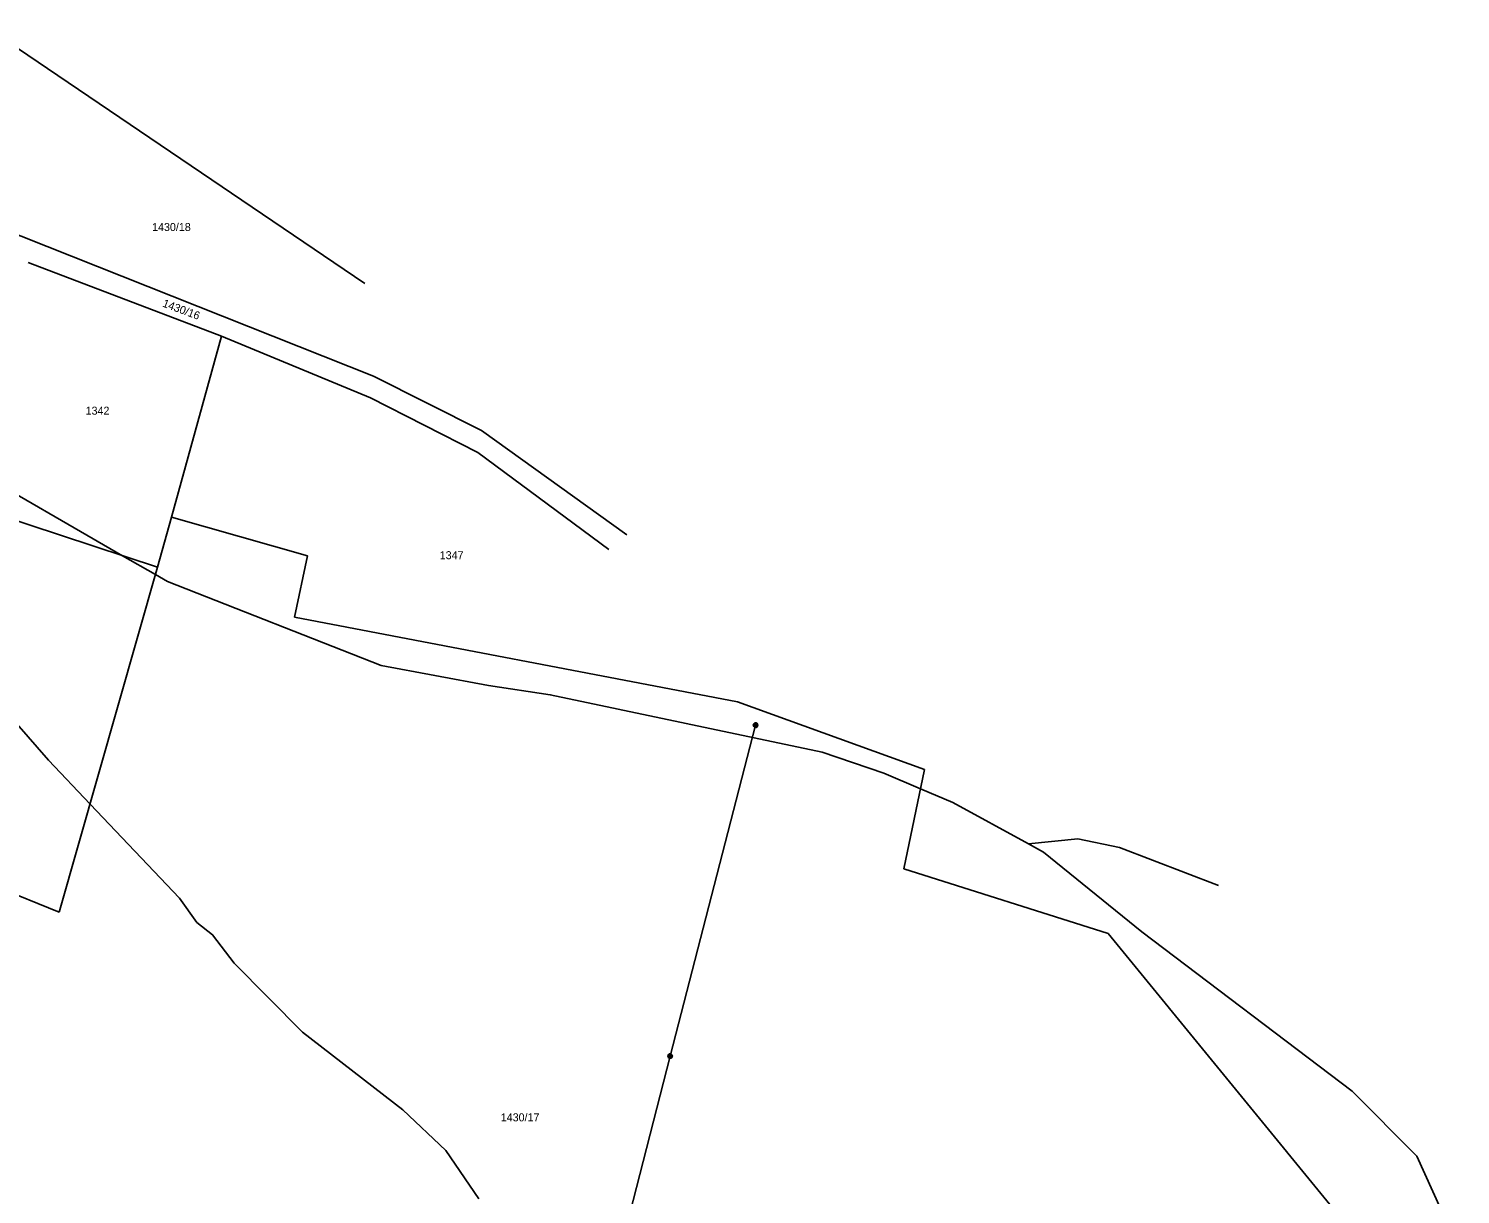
# Model space of a CAD drawing. Extents: x -789470 to -786707, y -1118640 to -1114455.
# Drawn here: x -787011.1 to -786706.9, y -1117950.7 to -1117702.9 of the extents above; entities that cross this region are included whole.
import ezdxf

# ---------------------------------------------------------------- set-up
doc = ezdxf.new("R2010")
doc.units = 0
for name, color, linetype in [('1', 7, 'Continuous'), ('11', 7, 'Continuous'), ('2', 7, 'Continuous'), ('6', 7, 'Continuous')]:
    doc.layers.add(name, color=color, linetype=linetype)

msp = doc.modelspace()

# ---------------------------------------------------------------- linework, layer by layer
at = {"layer": '1'}
for p, q in [((-786939.62, -1117757.05), (-787019.6, -1117702.92)), ((-787019.38, -1117744.35), (-786937.83, -1117776.81)), ((-786970.08, -1117768.29), (-787011.2, -1117752.61)), ((-786980.72, -1117806.77), (-786970.08, -1117768.29)), ((-786938.43, -1117781.41), (-786970.08, -1117768.29)), ((-786937.83, -1117776.81), (-786914.84, -1117788.3)), ((-786915.64, -1117792.98), (-786938.43, -1117781.41)), ((-786914.84, -1117788.3), (-786883.99, -1117810.47)), ((-786887.82, -1117813.58), (-786915.64, -1117792.98)), ((-787027.4, -1117802.98), (-786983.7, -1117817.36)), ((-786983.7, -1117817.36), (-786980.72, -1117806.77)), ((-786951.82, -1117814.97), (-786980.72, -1117806.77)), ((-786954.58, -1117828.02), (-786951.82, -1117814.97)), ((-787004.56, -1117890.66), (-786983.7, -1117817.36)), ((-786860.45, -1117845.95), (-786954.58, -1117828.02)), ((-786820.74, -1117860.37), (-786860.45, -1117845.95)), ((-786825.17, -1117881.49), (-786820.74, -1117860.37)), ((-787047.08, -1117873.45), (-787004.56, -1117890.66)), ((-786781.74, -1117895.23), (-786825.17, -1117881.49)), ((-786724.91, -1117964.6), (-786781.74, -1117895.23))]:
    msp.add_line(p, q, dxfattribs=at)
at = {"layer": '11'}
for points in [[(-787042.34, -1117785.36), (-787024.68, -1117795.55), (-786991.12, -1117814.92), (-786984.15, -1117818.94), (-786981.58, -1117820.43), (-786936.16, -1117838.26), (-786913.37, -1117842.53), (-786900.27, -1117844.49), (-786842.47, -1117856.66), (-786829.42, -1117861.15), (-786821.6, -1117864.46), (-786814.71, -1117867.37), (-786798.67, -1117876.14)], [(-787042.34, -1117785.36), (-787041.4, -1117793.03), (-787038.67, -1117815.46), (-787035.18, -1117823.62), (-787035.02, -1117823.99), (-787030.91, -1117830.84), (-787006.87, -1117858.4), (-786998.03, -1117867.71), (-786979.04, -1117887.72), (-786975.32, -1117892.87), (-786971.98, -1117895.48), (-786967.44, -1117901.49), (-786952.89, -1117916.16), (-786931.6, -1117932.67), (-786922.44, -1117941.31), (-786915.44, -1117951.6)], [(-786798.67, -1117876.14), (-786788.17, -1117875.1), (-786779.31, -1117876.97), (-786758.28, -1117885.01)], [(-786798.67, -1117876.14), (-786795.43, -1117877.91), (-786774.57, -1117894.83), (-786729.88, -1117928.73), (-786716.16, -1117942.54), (-786707.62, -1117961.32), (-786706.9, -1117968.1), (-786707.06, -1117976.56), (-786708.04, -1117983.3), (-786714.98, -1117999.9), (-786715.13, -1118000), (-786735.57, -1118013.5), (-786756.31, -1118027.27), (-786767.16, -1118036.26), (-786771.09, -1118040.37), (-786774.63, -1118045.35), (-786777.31, -1118050.34), (-786777.58, -1118060.06)]]:
    msp.add_lwpolyline(points, dxfattribs=at)
at = {"layer": '6'}
for p, q in [((-786856.64, -1117850.95), (-786874.81, -1117921.27)), ((-786874.81, -1117921.27), (-786892.47, -1117990.35))]:
    msp.add_line(p, q, dxfattribs=at)
for points in [[(-786856.79, -1117850.47), (-786856.48, -1117850.47), (-786856.23, -1117850.65), (-786856.13, -1117850.94), (-786856.23, -1117851.23), (-786856.48, -1117851.41), (-786856.79, -1117851.41), (-786857.04, -1117851.23), (-786857.14, -1117850.94), (-786857.04, -1117850.65), (-786856.79, -1117850.47), (-786856.76, -1117850.51), (-786856.52, -1117850.51), (-786856.36, -1117850.59), (-786856.92, -1117850.59), (-786857, -1117850.67), (-786856.28, -1117850.67), (-786856.28, -1117850.75), (-786857, -1117850.75), (-786857.04, -1117850.83), (-786856.24, -1117850.83), (-786856.2, -1117850.91), (-786857.08, -1117850.91), (-786857.08, -1117850.99), (-786856.2, -1117850.99), (-786856.23, -1117851.07), (-786857.04, -1117851.07), (-786857.03, -1117851.15), (-786856.22, -1117851.15), (-786856.27, -1117851.23), (-786856.99, -1117851.23), (-786856.91, -1117851.31), (-786856.35, -1117851.31), (-786856.46, -1117851.39), (-786856.8, -1117851.39)], [(-786874.96, -1117920.79), (-786874.65, -1117920.79), (-786874.4, -1117920.97), (-786874.3, -1117921.26), (-786874.4, -1117921.55), (-786874.65, -1117921.73), (-786874.96, -1117921.73), (-786875.21, -1117921.55), (-786875.31, -1117921.26), (-786875.21, -1117920.97), (-786874.96, -1117920.79), (-786874.93, -1117920.83), (-786874.69, -1117920.83), (-786874.53, -1117920.91), (-786875.09, -1117920.91), (-786875.17, -1117920.99), (-786874.45, -1117920.99), (-786874.45, -1117921.07), (-786875.17, -1117921.07), (-786875.21, -1117921.15), (-786874.41, -1117921.15), (-786874.37, -1117921.23), (-786875.25, -1117921.23), (-786875.25, -1117921.31), (-786874.37, -1117921.31), (-786874.4, -1117921.39), (-786875.21, -1117921.39), (-786875.2, -1117921.47), (-786874.39, -1117921.47), (-786874.44, -1117921.55), (-786875.16, -1117921.55), (-786875.08, -1117921.63), (-786874.52, -1117921.63), (-786874.63, -1117921.71), (-786874.97, -1117921.71)]]:
    msp.add_lwpolyline(points, dxfattribs=at)

# ---------------------------------------------------------------- texts
at = {"layer": '2'}
for s, p in [('1430/18', (-786984.85, -1117745.93)), ('1342', (-786998.97, -1117784.96)), ('1347', (-786923.74, -1117815.67)), ('1430/17', (-786910.77, -1117935.13))]:
    msp.add_text(s, height=1.7, dxfattribs=at).set_placement(p)
msp.add_text('1430/16', height=1.7, rotation=339.4775, dxfattribs=at).set_placement((-786982.77, -1117761.95))

doc.saveas('drawing.dxf')
